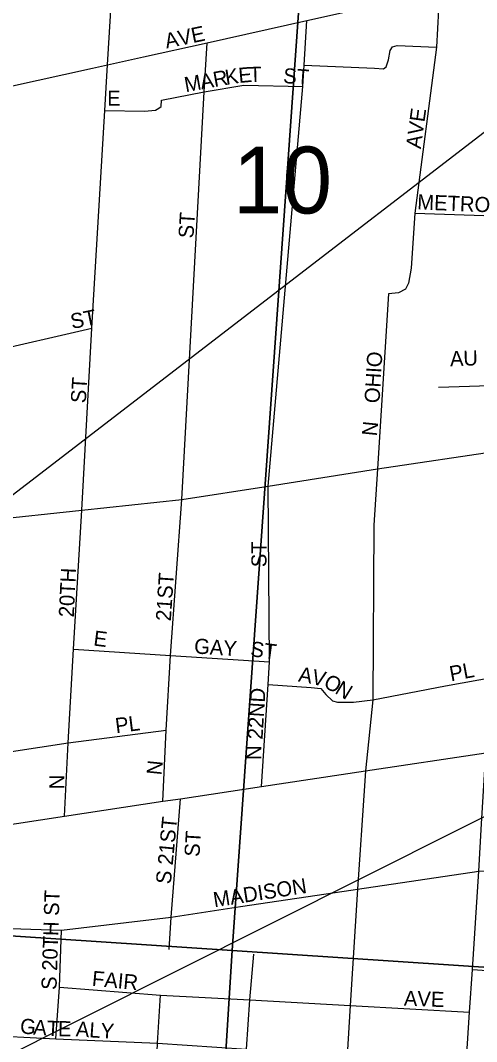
# Model space of a CAD drawing. Extents: x 0 to 34, y -6.2 to 22.
# Drawn here: x 8.065 to 8.351, y 18.119 to 18.759 of the extents above; entities that cross this region are included whole.
import ezdxf

# ---------------------------------------------------------------- set-up
doc = ezdxf.new("R2010")
doc.units = 0
for name, color, linetype in [('GM_X_City_Street', 7, 'Continuous'), ('GM_X_City_Street_Text', 7, 'Continuous'), ('GM_X_Section', 7, 'Continuous'), ('GM_X_Section_Text', 7, 'Continuous'), ('GM_X_US_Route', 7, 'Continuous'), ('SH_Data', 7, 'Continuous')]:
    doc.layers.add(name, color=color, linetype=linetype)

msp = doc.modelspace()

# ---------------------------------------------------------------- linework, layer by layer
at = {"layer": 'GM_X_City_Street'}
for points in [[(8.09288, 18.26028), (8.09519, 18.3062), (8.09854, 18.36482), (8.10377, 18.45197), (8.11002, 18.56601), (8.11805, 18.70259), (8.11968, 18.7312), (8.1235, 18.7929), (8.12786, 18.85649), (8.13026, 18.89751), (8.1332, 18.94504)], [(8.14239, 18.73617), (8.18227, 18.74489), (8.24469, 18.75894), (8.30704, 18.77302), (8.32785, 18.77745), (8.32814, 18.77751)], [(8.32785, 18.77745), (8.32608, 18.7423), (8.31235, 18.63809), (8.31007, 18.60377), (8.30843, 18.5943), (8.30649, 18.59053), (8.30229, 18.5883), (8.29583, 18.58763), (8.28899, 18.47797), (8.28679, 18.44272), (8.28612, 18.3332), (8.28148, 18.28853), (8.28085, 18.27924)], [(8.21629, 18.27891), (8.22045, 18.34278), (8.22134, 18.35696), (8.22058, 18.46707), (8.24229, 18.71749), (8.24305, 18.73093), (8.24469, 18.75894)], [(8.1544, 18.2697), (8.15655, 18.3141), (8.15922, 18.36096), (8.16636, 18.45877), (8.18046, 18.71417), (8.18227, 18.74489)], [(8.24305, 18.73093), (8.28708, 18.72912), (8.29283, 18.72859), (8.29452, 18.72983), (8.29599, 18.73434), (8.29689, 18.7402), (8.29847, 18.74235), (8.30131, 18.74334), (8.32608, 18.7423)], [(7.72601, 18.62794), (7.74471, 18.64436), (7.75252, 18.64682), (7.76759, 18.65156), (7.78409, 18.65514), (7.81606, 18.66276), (7.84681, 18.67178), (7.85444, 18.67339), (7.87957, 18.67872), (7.88893, 18.68071), (7.91322, 18.68585), (7.92824, 18.68855), (7.97409, 18.69875), (7.99605, 18.70341), (8.0035, 18.70498), (8.01031, 18.70646), (8.05824, 18.71749), (8.11034, 18.72912), (8.11968, 18.7312), (8.14239, 18.73617)], [(8.18046, 18.71417), (8.20517, 18.71851), (8.24229, 18.71749)], [(8.15364, 18.70902), (8.18046, 18.71417)], [(8.11805, 18.70259), (8.14294, 18.7021), (8.14746, 18.70252), (8.14981, 18.70285), (8.15185, 18.70403), (8.15332, 18.70514), (8.15364, 18.70902)], [(8.31235, 18.63809), (8.38064, 18.63585)], [(7.80951, 18.52321), (7.84363, 18.5218), (7.88701, 18.53418), (7.92037, 18.53349), (7.9553, 18.53882), (7.98702, 18.54874), (8.04261, 18.55067), (8.11002, 18.56601)], [(8.32719, 18.52911), (8.37233, 18.5305), (8.37506, 18.53081), (8.37852, 18.53121), (8.37891, 18.53125)], [(7.56292, 18.37635), (7.57672, 18.37829), (7.58468, 18.37941), (7.591, 18.3803), (7.59427, 18.38091), (7.62982, 18.38756), (7.67292, 18.39175), (7.74898, 18.40202), (7.80065, 18.40857), (7.84375, 18.41455), (7.87636, 18.42025), (7.91447, 18.42624), (7.98084, 18.43482), (8.02749, 18.44183), (8.04476, 18.44573), (8.10377, 18.45197), (8.16636, 18.45877), (8.22058, 18.46707), (8.28899, 18.47797), (8.36777, 18.48959), (8.36789, 18.48961)], [(8.09854, 18.36482), (8.15922, 18.36096), (8.22134, 18.35696)], [(8.28612, 18.3332), (8.33163, 18.34196), (8.37339, 18.3494)], [(8.22045, 18.34278), (8.24745, 18.34088), (8.25347, 18.34022), (8.25654, 18.33646), (8.26089, 18.33242), (8.26397, 18.3316), (8.27389, 18.33167), (8.28612, 18.3332)], [(8.02119, 18.29487), (8.09519, 18.3062), (8.15655, 18.3141)], [(8.30324, 17.50627), (8.3063, 17.56527), (8.31383, 17.65069), (8.31689, 17.69592), (8.31546, 17.74112), (8.31784, 17.77548), (8.32617, 17.82383), (8.33006, 17.88766), (8.328, 17.92274), (8.3364, 17.97961), (8.33874, 18.01052), (8.34076, 18.04298), (8.34276, 18.07512), (8.34663, 18.13739), (8.34848, 18.16421), (8.3525, 18.22577), (8.35422, 18.25539), (8.35686, 18.29982)], [(8.28085, 18.27924), (8.27644, 18.21452), (8.27182, 18.14156), (8.26998, 18.11035), (8.26777, 18.0794), (8.26562, 18.04728), (8.2634, 18.01441), (8.26144, 17.98359), (8.25994, 17.96268), (8.25735, 17.92566), (8.25502, 17.88939), (8.25083, 17.82744), (8.24261, 17.77785), (8.24013, 17.74287), (8.2422, 17.69834), (8.2392, 17.653), (8.23352, 17.5669), (8.22791, 17.50222)], [(8.15835, 18.17666), (8.15958, 18.19694), (8.16557, 18.27114)], [(8.27374, 18.21411), (8.27644, 18.21452), (8.3525, 18.22577), (8.43519, 18.22893), (8.49918, 18.23141)], [(8.05898, 18.18971), (8.09102, 18.18866), (8.15958, 18.19694), (8.20319, 18.20351), (8.27374, 18.21411)], [(8.08748, 18.1206), (8.08964, 18.15306), (8.09102, 18.18866)], [(8.18068, 17.79001), (8.18375, 17.82997), (8.18926, 17.88903), (8.19269, 17.92754), (8.19504, 17.96522), (8.1968, 17.98631), (8.19928, 18.01857), (8.20184, 18.05052), (8.20447, 18.08319), (8.20697, 18.11423), (8.20907, 18.14516), (8.21146, 18.17374)], [(8.34848, 18.16421), (8.43106, 18.15841), (8.49508, 18.1541), (8.5364, 18.15136), (8.56402, 18.14944), (8.57373, 18.14881), (8.62093, 18.14565), (8.63634, 18.14461), (8.72689, 18.1387), (8.76464, 18.13622), (8.8125, 18.13308)], [(8.08964, 18.15306), (8.15292, 18.14808), (8.20907, 18.14516), (8.27182, 18.14156), (8.34663, 18.13739)], [(8.14594, 18.0288), (8.14784, 18.05376), (8.14985, 18.08599), (8.15115, 18.11796), (8.15292, 18.14808)], [(8.0551, 18.12239), (8.08748, 18.1206), (8.15115, 18.11796), (8.20697, 18.11423), (8.26998, 18.11035)]]:
    msp.add_lwpolyline(points, dxfattribs=at)
at = {"layer": 'GM_X_Section'}
for points in [[(7.74778, 19.20365), (8.26811, 19.16854), (8.19802, 18.176), (7.67976, 18.21035)], [(8.26811, 19.16854), (8.78729, 19.13351), (8.7151, 18.14174), (8.19802, 18.176)], [(8.19802, 18.176), (8.1365, 17.19384), (7.62278, 17.23025), (7.67976, 18.21035)], [(8.7151, 18.14174), (8.649, 17.15751), (8.1365, 17.19384), (8.19802, 18.176)]]:
    msp.add_lwpolyline(points, close=True, dxfattribs=at)
at = {"layer": 'GM_X_US_Route'}
msp.add_lwpolyline([(7.77016, 18.21339), (7.80873, 18.21999), (7.81592, 18.22114), (7.82226, 18.22216), (7.88576, 18.22974), (7.90337, 18.23243), (7.96364, 18.24118), (8.01947, 18.24955), (8.06265, 18.25562), (8.09288, 18.26028), (8.1544, 18.2697), (8.16557, 18.27114), (8.21629, 18.27891), (8.28148, 18.28853), (8.35686, 18.29982), (8.36307, 18.30421), (8.43444, 18.31495), (8.43635, 18.31524), (8.48787, 18.3231), (8.5004, 18.32501), (8.58081, 18.33728), (8.64788, 18.34739), (8.72532, 18.35906)], dxfattribs=at)
at = {"layer": 'SH_Data'}
msp.add_lwpolyline([(10.0459, 19.98884), (6.75174, 17.45513), (10.0459, 19.10806)], close=True, dxfattribs=at)

# ---------------------------------------------------------------- texts
at = {"layer": 'GM_X_City_Street_Text'}
for s, rotation, p in [('AVE', 11.69061, (8.15671, 18.74136)), ('K', 8.58701, (8.19415, 18.71855)), ('E', 5.1522, (8.20224, 18.71977)), ('T', 1.7174, (8.20873, 18.72036)), ('ST', 356.17335, (8.22969, 18.71973)), ('M', 10.30441, (8.16881, 18.71394)), ('A', 10.30441, (8.17865, 18.71573)), ('R', 10.30441, (8.18685, 18.71722)), ('E', 0.00001, (8.11957, 18.70556)), ('AVE', 82.15076, (8.31614, 18.67819)), ('METRO', 357.66397, (8.31381, 18.64056)), ('ST', 86.42535, (8.17363, 18.62223)), ('ST', 11.30433, (8.09756, 18.56553)), ('OHIO', 86.72506, (8.29029, 18.51888)), ('A', 1.85818, (8.33461, 18.54224)), ('U', 1.83634, (8.34294, 18.54251)), ('ST', 86.42535, (8.10613, 18.51889)), ('N', 84.29157, (8.28863, 18.49813)), ('ST', 90, (8.21945, 18.41628)), ('20TH', 87.26997, (8.09862, 18.3847)), ('21ST', 86.18785, (8.15946, 18.38224)), ('E', 352.87835, (8.11062, 18.36722)), ('GAY', 356.18786, (8.17386, 18.36223)), ('ST', 352.39486, (8.20897, 18.36055)), ('A', 350.13887, (8.23901, 18.34471)), ('V', 346.00616, (8.24705, 18.34332)), ('PL', 10.61471, (8.33508, 18.3447)), ('O', 331.56749, (8.25455, 18.34153)), ('N', 328.57147, (8.26176, 18.33763)), ('22ND', 86.63541, (8.21696, 18.30805)), ('PL', 7.12165, (8.12518, 18.31221)), ('N', 90, (8.21613, 18.29545)), ('N', 84.29157, (8.15363, 18.28563)), ('N', 90, (8.09279, 18.27711)), ('S 21ST', 84.43089, (8.15946, 18.21729)), ('ST', 86.42621, (8.17738, 18.23455)), ('MADISON', 8.88264, (8.18679, 18.20304)), ('S 20TH ST', 88.15147, (8.08779, 18.1512)), ('FAIR', 354.63994, (8.10974, 18.15389)), ('AVE', 358.0261, (8.30546, 18.1414)), ('G', 355.40516, (8.06469, 18.12406)), ('A', 355.38338, (8.073, 18.12339)), ('T', 356.79685, (8.08155, 18.1227)), ('E', 359.25456, (8.08866, 18.12232)), ('ALY', 356.05688, (8.09969, 18.12223))]:
    msp.add_text(s, height=0.00947, rotation=rotation, dxfattribs=at).set_placement(p)
at = {"layer": 'GM_X_Section_Text'}
msp.add_text('10', height=0.041856, rotation=0.00001, dxfattribs=at).set_placement((8.19832, 18.63801))

doc.saveas('drawing.dxf')
